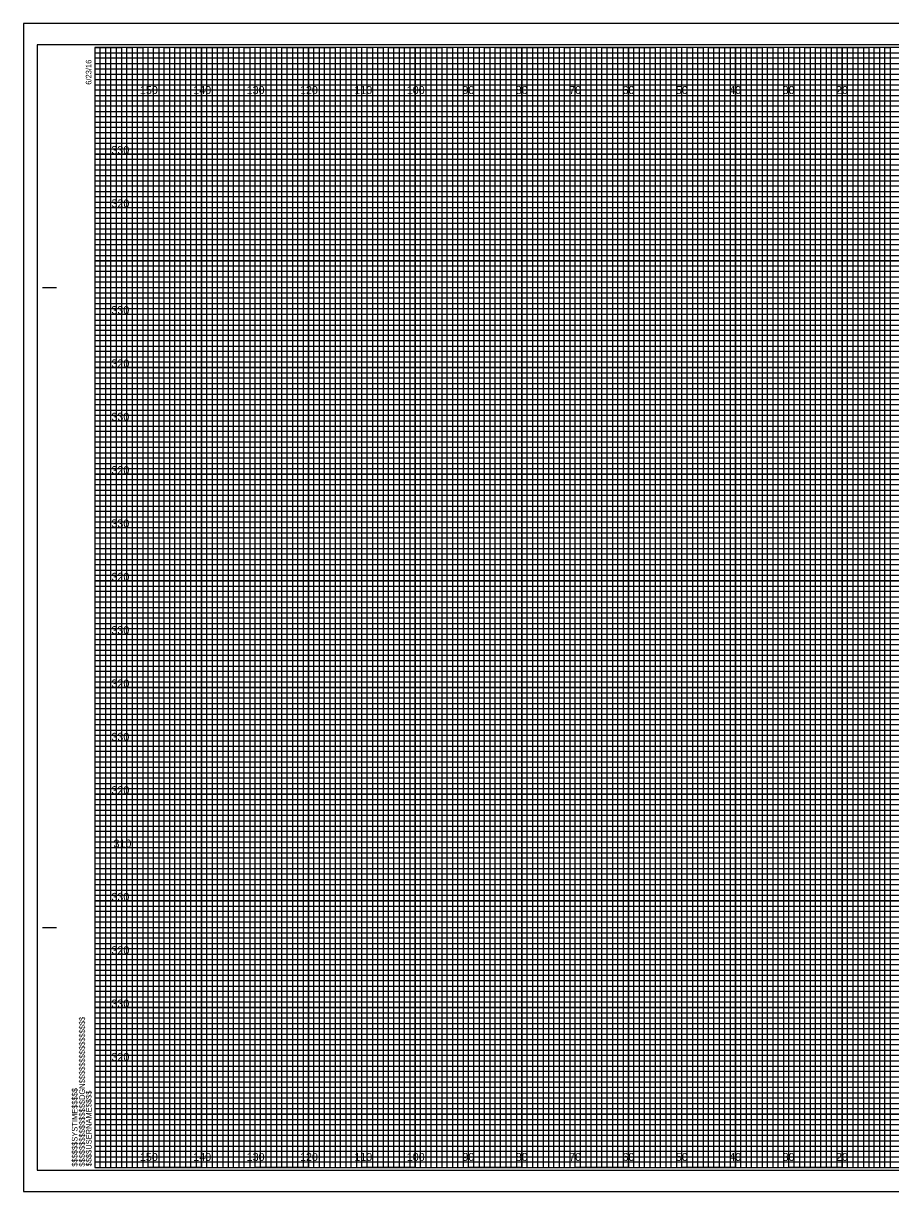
# Model space of a CAD drawing. Extents: x -13 to 323, y 656 to 874.
# Drawn here: x -13.4 to 149.1, y 655.5 to 874.5 of the extents above; entities that cross this region are included whole.
import ezdxf

# ---------------------------------------------------------------- set-up
doc = ezdxf.new("R2010")
doc.units = 0
for name, color, linetype in [('Prop XS Elevation Labels', 7, 'Continuous'), ('Prop XS Offset Labels', 7, 'Continuous'), ('Sheet Cross Section CELL', 7, 'Continuous'), ('Sheet Cross Section Grid Major CELL', 7, 'Continuous'), ('Sheet Cross Section Grid Middle CELL', 7, 'Continuous'), ('Sheet Cross Section Grid Minor 1 CELL', 7, 'Continuous'), ('Sheet Cross Section Grid Minor 2 CELL', 7, 'Continuous'), ('Sheet Cutting Line CELL', 7, 'Continuous'), ('Sheet DOT Grid CELL', 7, 'Continuous'), ('Sheet Plot Border Inside CELL', 7, 'Continuous'), ('Sheet Plot Border Outside CELL', 7, 'Continuous')]:
    doc.layers.add(name, color=color, linetype=linetype)

msp = doc.modelspace()

# ---------------------------------------------------------------- linework, layer by layer
at = {"layer": 'Sheet Cross Section CELL'}
for p, q in [((-9.8, 825), (-7.3, 825)), ((-9.7, 825), (-7.2, 825)), ((-9.8, 705), (-7.3, 705)), ((-9.7, 705), (-7.2, 705)), ((0, 660), (0, 660)), ((0, 660), (0, 660)), ((0, 660), (0, 660)), ((0, 660), (0, 660)), ((0, 660), (0, 660)), ((0, 660), (0, 660)), ((0, 660), (0, 660))]:
    msp.add_line(p, q, dxfattribs=at)
msp.add_lwpolyline([(320, 870), (0, 870), (0, 660), (320, 660)], close=True, dxfattribs=at)
at = {"layer": 'Sheet Cross Section Grid Major CELL'}
for p, q in [((10, 870), (0, 870)), ((10, 660), (10, 870)), ((30, 870), (20, 870)), ((20, 870), (20, 660)), ((30, 660), (30, 870)), ((50, 870), (40, 870)), ((40, 870), (40, 660)), ((50, 660), (50, 870)), ((70, 870), (60, 870)), ((60, 870), (60, 660)), ((70, 660), (70, 870)), ((90, 870), (80, 870)), ((80, 870), (80, 660)), ((90, 660), (90, 870)), ((110, 870), (100, 870)), ((100, 870), (100, 660)), ((110, 660), (110, 870)), ((130, 870), (120, 870)), ((120, 870), (120, 660)), ((130, 660), (130, 870)), ((150, 870), (140, 870)), ((140, 870), (140, 660)), ((20, 660), (10, 660)), ((40, 660), (30, 660)), ((60, 660), (50, 660)), ((80, 660), (70, 660)), ((100, 660), (90, 660)), ((120, 660), (110, 660)), ((140, 660), (130, 660))]:
    msp.add_line(p, q, dxfattribs=at)
for points in [[(0, 860), (320, 860), (320, 850), (0, 850)], [(0, 840), (320, 840), (320, 830), (0, 830)], [(0, 820), (320, 820), (320, 810), (0, 810)], [(0, 800), (320, 800), (320, 790), (0, 790)], [(0, 780), (320, 780), (320, 770), (0, 770)], [(0, 760), (320, 760), (320, 750), (0, 750)], [(0, 740), (320, 740), (320, 730), (0, 730)], [(0, 720), (320, 720), (320, 710), (0, 710)], [(0, 700), (320, 700), (320, 690), (0, 690)], [(0, 680), (320, 680), (320, 670), (0, 670)]]:
    msp.add_lwpolyline(points, dxfattribs=at)
at = {"layer": 'Sheet Cross Section Grid Middle CELL'}
for points in [[(0, 870), (5, 870), (5, 660), (15, 660), (15, 870), (25, 870), (25, 660), (35, 660), (35, 870), (45, 870), (45, 660), (55, 660), (55, 870), (65, 870), (65, 660), (75, 660), (75, 870), (85, 870), (85, 660), (95, 660), (95, 870), (105, 870), (105, 660), (115, 660), (115, 870), (125, 870), (125, 660), (135, 660), (135, 870), (145, 870), (145, 660), (155, 660)], [(0, 865), (275, 865)], [(0, 845), (320, 845), (320, 855), (0, 855)], [(0, 825), (320, 825), (320, 835), (0, 835)], [(0, 805), (320, 805), (320, 815), (0, 815)], [(0, 785), (320, 785), (320, 795), (0, 795)], [(0, 765), (320, 765), (320, 775), (0, 775)], [(0, 745), (320, 745), (320, 755), (0, 755)], [(0, 725), (320, 725), (320, 735), (0, 735)], [(0, 705), (320, 705), (320, 715), (0, 715)], [(0, 685), (320, 685), (320, 695), (0, 695)], [(0, 665), (320, 665), (320, 675), (0, 675)]]:
    msp.add_lwpolyline(points, dxfattribs=at)
at = {"layer": 'Sheet Cross Section Grid Minor 1 CELL'}
for p, q in [((0, 869), (260, 869)), ((260, 867.98), (0, 867.98)), ((0, 867.98), (0, 867)), ((0, 867), (260, 867)), ((260, 865.89), (0, 865.89)), ((0, 865.89), (0, 864)), ((0, 864), (320, 864))]:
    msp.add_line(p, q, dxfattribs=at)
for points in [[(0, 863), (270, 863), (320, 863), (320, 862), (0, 862)], [(0, 861), (320, 861), (320, 859), (0, 859)], [(0, 858), (320, 858), (320, 857), (0, 856.98)], [(0, 856), (320, 856), (320, 854), (0, 854)], [(0, 853), (320, 853), (320, 852), (0, 852)], [(0, 851), (320, 851), (320, 849), (0, 849)], [(0, 848), (320, 848), (320, 847), (0, 847)], [(0, 846), (320, 846), (320, 844), (0, 844)], [(0, 843), (320, 843), (320, 842), (0, 842)], [(0, 841), (320, 841), (320, 839), (0, 839)], [(0, 838), (320, 838), (320, 837), (0, 837)], [(0, 836), (320, 836), (320, 833.95), (320, 833), (320, 832), (0, 832)], [(0, 834), (320, 834), (320, 833), (0, 833)], [(0, 831), (320, 831), (320, 829), (0, 829.03)], [(0, 829.03), (320, 829), (320, 828), (0, 828)], [(0, 827), (320, 827), (320, 826), (0, 826)], [(0, 824), (320, 824), (320, 823), (0, 823)], [(0, 822), (320, 822), (320, 821), (0, 821)], [(-0.07, 818.89), (320, 818.89), (320, 817.88), (-0.07, 817.88)], [(0, 817), (320, 817), (320, 816), (0, 816)], [(0, 814), (320, 814), (320, 813), (0, 813)], [(0, 812), (320, 812), (320, 811), (0, 811)], [(0, 809), (320, 809), (320, 808), (0, 808)], [(0, 807), (320, 807), (320, 806), (0, 806)], [(0, 804), (320, 804), (320, 803), (0, 803)], [(0, 802), (320, 802), (320, 801), (0, 801)], [(0, 799), (320, 799), (319.99, 797.98), (0, 798)], [(0, 797), (320, 797), (320, 796), (0, 796)], [(0, 794), (320, 794), (320, 793), (0, 793)], [(0, 792), (320, 792), (320, 791), (0, 791)], [(0, 789), (320, 789), (320, 788), (0, 788)], [(0, 787), (320, 787), (320, 786), (0, 786)], [(0, 784), (320, 784), (320, 783), (0, 783)], [(0, 782), (320, 782), (320, 781), (0, 781)], [(0, 779), (320, 779), (320, 778), (0, 778)], [(0, 776.99), (320.07, 776.91), (320, 776), (0, 776)], [(0, 774), (320, 774), (320, 773), (0, 773)], [(0, 772), (320, 772), (320, 771), (0, 771)], [(0, 769), (320, 769), (320, 768), (0, 768)], [(0, 767), (320, 767), (320, 766), (0, 766)], [(0, 764), (320, 764), (320, 763), (0, 763)], [(0, 762), (320, 762), (320, 761), (0, 761)], [(0, 759), (320, 759), (320, 758), (0, 758)], [(0, 757), (320, 757), (320, 756), (0, 756)], [(0, 754), (320, 754), (320, 753), (0, 753)], [(0, 752), (320, 752), (320, 751), (0, 751)], [(0, 749), (320, 749), (320, 748), (0, 748)], [(0, 747), (320, 747), (320, 746), (0, 746)], [(0, 744), (320, 744), (320, 743), (0, 743)], [(0, 742), (320, 742), (320, 741), (0, 741)], [(0, 739), (320, 739), (319.99, 737.98), (0, 738)], [(0, 737), (320, 737), (320, 736), (0, 736)], [(0, 734), (320, 734), (320, 733), (0, 733)], [(0, 732), (320, 732), (320, 731), (0, 731)], [(0, 729), (320, 729), (320, 728), (0, 728)], [(0, 727), (320, 727), (320, 726), (0, 726)], [(0, 724), (320, 724), (320, 723), (0, 723)], [(0, 722), (320, 722), (320, 721), (0, 721)], [(0, 719), (320, 719), (320, 718), (0, 718)], [(0, 716.99), (320.07, 716.91), (320, 716), (0, 716)], [(0, 714), (320, 714), (320, 713), (0, 713)], [(0, 712), (320, 712), (320, 711), (0, 711)], [(0, 709), (320, 709), (320, 708), (0, 708)], [(0, 707), (320, 707), (320, 706), (0, 706)], [(0, 704), (320, 704), (320, 703), (0, 703)], [(0, 702), (320, 702), (320, 701), (0, 701)], [(0, 699), (320, 699), (320, 698), (0, 698)], [(0, 697), (320, 697), (320, 696), (0, 696)], [(0, 694), (320, 694), (320, 693), (0, 693)], [(0, 692), (320, 692), (320, 691), (0, 691)], [(0, 689), (320, 689), (320, 688), (0, 688)], [(0, 687), (320, 687), (320, 686), (0, 686)], [(0, 684), (320, 684), (320, 683), (0, 683)], [(0, 682), (320, 682), (320, 681), (0, 681)], [(0, 679), (320, 679), (320, 678), (0, 678)], [(0, 677), (320, 677), (320, 676), (0, 676)], [(0, 674), (320, 674), (320, 673), (0, 673)], [(0, 672), (320, 672), (320, 671), (0, 671)], [(0, 669), (320, 669), (320, 668), (0, 668)], [(0, 667), (320, 667), (320, 666), (0, 666)], [(0, 664), (320, 664), (320, 663), (0, 663)], [(0, 662), (320, 662), (320, 661), (0, 661)]]:
    msp.add_lwpolyline(points, dxfattribs=at)
at = {"layer": 'Sheet Cross Section Grid Minor 2 CELL'}
for points in [[(0, 660), (1, 660), (1, 870), (2, 870), (2, 660)], [(2, 660), (3, 660), (3, 870), (4, 870), (4, 660)], [(5, 660), (6, 660), (6, 870), (7, 870), (7, 660)], [(7, 660), (8, 660), (8, 870), (9, 870), (9, 660)], [(10, 660), (11, 660), (11, 870), (12, 870), (12, 660)], [(12, 660), (13, 660), (13, 870), (14, 870), (14, 660)], [(15, 660), (16, 660), (16, 870), (17, 870), (17, 660)], [(17, 660), (18, 660), (18, 870), (19, 870), (19, 660)], [(20, 660), (21, 660), (21, 870), (22, 870), (22, 660)], [(22, 660), (23, 660), (23, 870), (24, 870), (24, 660)], [(25, 660), (26, 660), (26, 870), (27, 870), (27, 660)], [(27, 660), (28, 660), (28, 870), (29, 870), (29, 660)], [(30, 660), (31, 660), (31, 870), (32, 870), (32, 660)], [(32, 660), (33, 660), (33, 870), (34, 870), (34, 660)], [(35, 660), (36, 660), (36, 870), (37, 870), (37, 660)], [(37, 660), (38, 660), (38, 870), (39, 870), (39, 660)], [(40, 660), (41, 660), (41, 870), (42, 870), (42, 660)], [(42, 660), (43, 660), (43, 870), (44, 870), (44, 660)], [(45, 660), (46, 660), (46, 870), (47, 870), (47, 660)], [(47, 660), (48, 660), (48, 870), (49, 870), (49, 660)], [(50, 660), (51, 660), (51, 870), (52, 870), (52, 660)], [(52, 660), (53, 660), (53, 870), (54, 870), (54, 660)], [(55, 660), (56, 660), (56, 870), (57, 870), (57, 660)], [(57, 660), (58, 660), (58, 870), (59, 870), (59, 660)], [(60, 660), (61, 660), (61, 870), (62, 870), (62, 660)], [(62, 660), (63, 660), (63, 870), (64, 870), (64, 660)], [(65, 660), (66, 660), (66, 870), (67, 870), (67, 660)], [(67, 660), (68, 660), (68, 870), (69, 870), (69, 660)], [(70, 660), (71, 660), (71, 870), (72, 870), (72, 660)], [(72, 660), (73, 660), (73, 870), (74, 870), (74, 660)], [(75, 660), (76, 660), (76, 870), (77, 870), (77, 660)], [(77, 660), (78, 660), (78, 870), (79, 870), (79, 660)], [(80, 660), (81, 660), (81, 870), (82, 870), (82, 660)], [(82, 660), (83, 660), (83, 870), (84, 870), (84, 660)], [(85, 660), (86, 660), (86, 870), (87, 870), (87, 660)], [(87, 660), (88, 660), (88, 870), (89, 870), (89, 660)], [(90, 660), (91, 660), (91, 870), (92, 870), (92, 660)], [(92, 660), (93, 660), (93, 870), (94, 870), (94, 660)], [(95, 660), (96, 660), (96, 870), (97, 870), (97, 660)], [(97, 660), (98, 660), (98, 870), (99, 870), (99, 660)], [(100, 660), (101, 660), (101, 870), (102, 870), (102, 660)], [(102, 660), (103, 660), (103, 870), (104, 870), (104, 660)], [(105, 660), (106, 660), (106, 870), (107, 870), (107, 660)], [(107, 660), (108, 660), (108, 870), (109, 870), (109, 660)], [(110, 660), (111, 660), (111, 870), (112, 870), (112, 660)], [(112, 660), (113, 660), (113, 870), (114, 870), (114, 660)], [(115, 660), (116, 660), (116, 870), (117, 870), (117, 660)], [(117, 660), (118, 660), (118, 870), (119, 870), (119, 660)], [(120, 660), (121, 660), (121, 870), (122, 870), (122, 660)], [(122, 660), (123, 660), (123, 870), (124, 870), (124, 660)], [(125, 660), (126, 660), (126, 870), (127, 870), (127, 660)], [(127, 660), (128, 660), (128, 870), (129, 870), (129, 660)], [(130, 660), (131, 660), (131, 870), (132, 870), (132, 660)], [(132, 660), (133, 660), (133, 870), (134, 870), (134, 660)], [(135, 660), (136, 660), (136, 870), (137, 870), (137, 660)], [(137, 660), (138, 660), (138, 870), (139, 870), (139, 660)], [(140, 660), (141, 660), (141, 870), (142, 870), (142, 660)], [(142, 660), (143, 660), (143, 870), (144, 870), (144, 660)], [(145, 660), (146, 660), (146, 870), (147, 870), (147, 660)], [(147, 660), (148, 660), (148, 870), (149, 870), (149, 660)]]:
    msp.add_lwpolyline(points, dxfattribs=at)
at = {"layer": 'Sheet Cutting Line CELL'}
for p, q in [((323.3, 874.5), (-13.4, 874.5)), ((-13.4, 874.5), (-13.4, 655.5)), ((-13.4, 655.5), (323.3, 655.5))]:
    msp.add_line(p, q, dxfattribs=at)
at = {"layer": 'Sheet DOT Grid CELL'}
for p, q in [((10, 660), (10, 870)), ((20, 660), (20, 870)), ((30, 660), (30, 870)), ((40, 660), (40, 870)), ((50, 660), (50, 870)), ((60, 660), (60, 870)), ((70, 660), (70, 870)), ((80, 660), (80, 870)), ((90, 660), (90, 870)), ((100, 660), (100, 870)), ((110, 660), (110, 870)), ((120, 660), (120, 870)), ((130, 660), (130, 870)), ((140, 660), (140, 870)), ((0, 860), (320, 860)), ((0, 850), (320, 850)), ((0, 840), (320, 840)), ((0, 830), (320, 830)), ((0, 820), (320, 820)), ((0, 810), (320, 810)), ((0, 800), (320, 800)), ((0, 790), (320, 790)), ((0, 780), (320, 780)), ((0, 770), (320, 770)), ((0, 760), (320, 760)), ((0, 750), (320, 750)), ((0, 740), (320, 740)), ((0, 730), (320, 730)), ((0, 720), (320, 720)), ((0, 710), (320, 710)), ((0, 700), (320, 700)), ((0, 690), (320, 690)), ((0, 680), (320, 680)), ((0, 670), (320, 670))]:
    msp.add_line(p, q, dxfattribs=at)
at = {"layer": 'Sheet Plot Border Inside CELL'}
msp.add_lwpolyline([(-10.8, 659.5), (322.4, 659.5), (322.4, 870.5), (-10.8, 870.5)], close=True, dxfattribs=at)
at = {"layer": 'Sheet Plot Border Outside CELL'}
msp.add_lwpolyline([(-13.4, 655.5), (323.3, 655.5), (323.3, 874.5), (-13.4, 874.5)], close=True, dxfattribs=at)

# ---------------------------------------------------------------- texts
at = {"layer": 'Prop XS Elevation Labels'}
for s, p in [('330', (3.1, 850)), ('320', (3.11, 840)), ('330', (3.1, 820)), ('320', (3.11, 810)), ('330', (3.1, 800)), ('320', (3.11, 790)), ('330', (3.1, 780)), ('320', (3.11, 770)), ('330', (3.1, 760)), ('320', (3.11, 750)), ('330', (3.1, 740)), ('320', (3.11, 730)), ('310', (3.49, 720)), ('330', (3.1, 710)), ('320', (3.11, 700)), ('330', (3.1, 690)), ('320', (3.11, 680))]:
    msp.add_text(s, height=1.5, dxfattribs=at).set_placement(p)
at = {"layer": 'Prop XS Offset Labels'}
for s, p in [('150', (8.44, 861.25)), ('140', (18.44, 861.25)), ('130', (28.44, 861.25)), ('120', (38.44, 861.25)), ('110', (48.62, 861.25)), ('100', (58.44, 861.25)), ('90', (68.86, 861.25)), ('80', (78.86, 861.25)), ('70', (88.86, 861.25)), ('60', (98.86, 861.25)), ('50', (108.86, 861.25)), ('40', (118.86, 861.25)), ('30', (128.86, 861.25)), ('20', (138.86, 861.25)), ('150', (8.44, 661.25)), ('140', (18.44, 661.25)), ('130', (28.44, 661.25)), ('120', (38.44, 661.25)), ('110', (48.62, 661.25)), ('100', (58.44, 661.25)), ('90', (68.86, 661.25)), ('80', (78.86, 661.25)), ('70', (88.86, 661.25)), ('60', (98.86, 661.25)), ('50', (108.86, 661.25)), ('40', (118.86, 661.25)), ('30', (128.86, 661.25)), ('20', (138.86, 661.25))]:
    msp.add_text(s, height=1.5, dxfattribs=at).set_placement(p)
at = {"layer": 'Sheet Cross Section CELL'}
for s, p in [('6/23/16', (-0.65, 863)), ('$$$$$$$$$$$$$$$$DGN$$$$$$$$$$$$$$$$', (-1.88, 660.18)), ('$$$$$$SYSTIME$$$$$', (-3.26, 660.18)), ('$$$$USERNAME$$$$', (-0.62, 660.23))]:
    msp.add_text(s, height=1.05, rotation=90, dxfattribs=at).set_placement(p)

doc.saveas('drawing.dxf')
